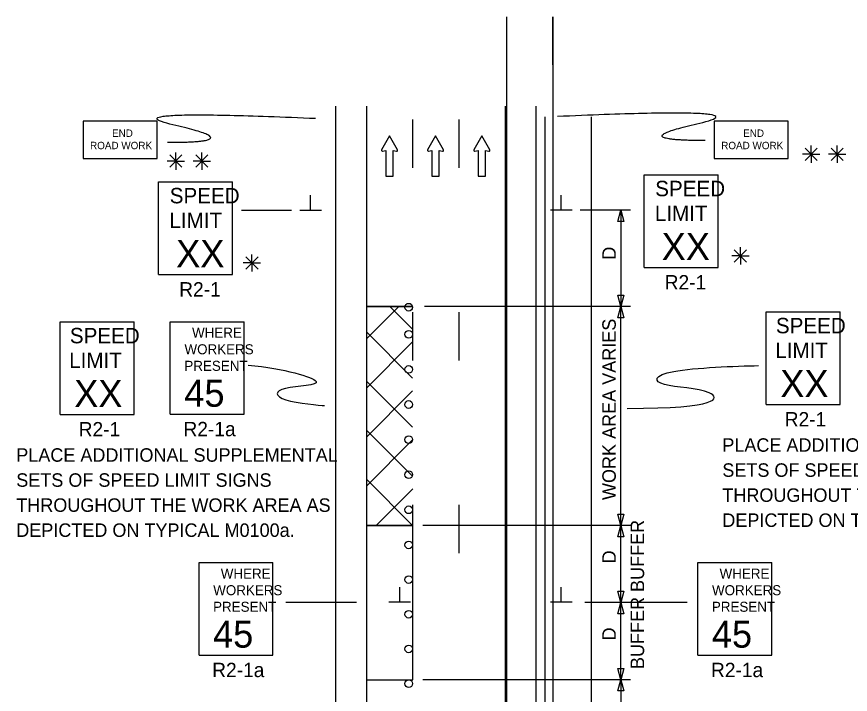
# Model space of a CAD drawing. Extents: x 16590 to 19504, y 5703 to 6974.
# Drawn here: x 16726.2 to 17159.2, y 6622.4 to 6974.1 of the extents above; entities that cross this region are included whole.
import ezdxf

# ---------------------------------------------------------------- set-up
doc = ezdxf.new("R2010")
doc.units = 0
for name, color, linetype in [('ALI_LEGAL_EX', 7, 'Continuous'), ('MT_SCRATCH_LEVEL_E', 7, 'Continuous'), ('PAVT_EDGE_EX', 7, 'Continuous'), ('TRAFFIC_SIGNS_PR', 7, 'Continuous'), ('TYPICAL_TEXT_DIMEN_PR', 7, 'Continuous')]:
    doc.layers.add(name, color=color, linetype=linetype)

msp = doc.modelspace()

# ---------------------------------------------------------------- linework, layer by layer
at = {"layer": 'ALI_LEGAL_EX'}
for p, q in [((16980.68, 6974.12), (16980.68, 6155.98)), ((17004.68, 6974.12), (17004.68, 6155.98)), ((17000.61, 6922.21), (17000.61, 6058.3)), ((17024.61, 6922.21), (17024.61, 6058.3))]:
    msp.add_line(p, q, dxfattribs=at)
for points in [[(17004.68, 6949.12), (17004.68, 6974.12)], [(16931.89, 6920.69), (16931.89, 6895.69)], [(16955.89, 6920.69), (16955.89, 6895.69)], [(16931.89, 6820.69), (16931.89, 6795.69)], [(16955.89, 6820.69), (16955.89, 6795.69)], [(16931.89, 6720.69), (16931.89, 6695.69)], [(16955.89, 6720.69), (16955.89, 6695.69)]]:
    msp.add_lwpolyline(points, dxfattribs=at)
at = {"layer": 'MT_SCRATCH_LEVEL_E'}
for p, q in [((16919.89, 6912.2), (16915.78, 6904.96)), ((16924.03, 6904.96), (16919.89, 6912.2)), ((16943.79, 6912.2), (16939.68, 6904.96)), ((16947.94, 6904.96), (16943.79, 6912.2)), ((16967.84, 6912.2), (16963.73, 6904.96)), ((16971.99, 6904.96), (16967.84, 6912.2)), ((16916.26, 6904.28), (16918.04, 6904.59)), ((16918.04, 6904.59), (16918.04, 6891.34)), ((16921.78, 6891.34), (16921.78, 6904.59)), ((16921.78, 6904.59), (16923.56, 6904.28)), ((16940.16, 6904.28), (16941.94, 6904.59)), ((16941.94, 6904.59), (16941.94, 6891.34)), ((16945.68, 6891.34), (16945.68, 6904.59)), ((16945.68, 6904.59), (16947.46, 6904.28)), ((16964.22, 6904.28), (16965.99, 6904.59)), ((16965.99, 6904.59), (16965.99, 6891.34)), ((16969.73, 6891.34), (16969.73, 6904.59)), ((16969.73, 6904.59), (16971.51, 6904.28)), ((16918.04, 6891.34), (16921.78, 6891.34)), ((16941.94, 6891.34), (16945.68, 6891.34)), ((16965.99, 6891.34), (16969.73, 6891.34))]:
    msp.add_line(p, q, dxfattribs=at)
for centre, start, end in [((16916.18, 6904.74), 150.4248, 279.9638), ((16923.62, 6904.74), 260.0362, 29.7731), ((16940.09, 6904.74), 150.4248, 279.9638), ((16947.53, 6904.74), 260.0362, 29.7731), ((16964.14, 6904.74), 150.4248, 279.9638), ((16971.58, 6904.74), 260.0362, 29.7731)]:
    msp.add_arc(centre, 0.463, start, end, dxfattribs=at)
at = {"layer": 'PAVT_EDGE_EX'}
for p, q in [((16891.89, 6927.73), (16891.89, 6507.47)), ((16907.89, 6927.73), (16907.89, 6507.47)), ((16979.89, 6927.73), (16979.89, 6507.47)), ((16995.89, 6927.73), (16995.89, 6507.47)), ((16907.89, 6823.76), (16931.89, 6823.76)), ((16907.89, 6806.86), (16924.79, 6823.76)), ((16931.98, 6823.76), (16907.98, 6823.76)), ((16931.89, 6811.94), (16920.07, 6823.76)), ((16931.89, 6786.49), (16907.89, 6810.49)), ((16907.89, 6781.4), (16931.89, 6805.4)), ((16931.89, 6761.03), (16907.89, 6785.03)), ((16907.89, 6755.95), (16931.89, 6779.95)), ((16931.89, 6735.58), (16907.89, 6759.58)), ((16907.89, 6730.49), (16931.89, 6754.49)), ((16931.89, 6710.12), (16907.89, 6734.12)), ((16912.88, 6710.03), (16931.98, 6729.12)), ((16931.89, 6710.03), (16907.89, 6710.03)), ((16931.98, 6710.03), (16907.98, 6710.03)), ((16907.98, 6710.03), (16931.98, 6710.03))]:
    msp.add_line(p, q, dxfattribs=at)
msp.add_lwpolyline([(16931.94, 6710.13), (16907.89, 6710.13), (16907.89, 6630.03), (16931.94, 6630.03)], close=True, dxfattribs=at)
at = {"layer": 'TRAFFIC_SIGNS_PR'}
for p, q in [((17052.11, 6892.08), (17090.56, 6892.08)), ((17052.11, 6844.02), (17052.11, 6892.08)), ((17090.56, 6844.02), (17090.56, 6892.08)), ((16799.93, 6888.4), (16838.38, 6888.4)), ((16799.93, 6840.34), (16799.93, 6888.4)), ((16838.38, 6840.34), (16838.38, 6888.4)), ((17052.11, 6844.02), (17090.56, 6844.02)), ((16799.93, 6840.34), (16838.38, 6840.34)), ((17115.56, 6820.92), (17153.96, 6820.92)), ((17115.56, 6772.92), (17115.56, 6820.92)), ((17153.96, 6772.92), (17153.96, 6820.92)), ((16748.8, 6815.74), (16787.2, 6815.74)), ((16748.8, 6767.74), (16748.8, 6815.74)), ((16787.2, 6767.74), (16787.2, 6815.74)), ((16806, 6815.83), (16844.4, 6815.83)), ((16806, 6767.83), (16806, 6815.83)), ((16844.4, 6767.83), (16844.4, 6815.83)), ((17115.56, 6772.92), (17153.96, 6772.92)), ((16748.8, 6767.74), (16787.2, 6767.74)), ((16806, 6767.83), (16844.4, 6767.83)), ((16820.92, 6690.79), (16859.32, 6690.79)), ((16820.92, 6642.79), (16820.92, 6690.79)), ((16859.32, 6642.79), (16859.32, 6690.79)), ((17080.02, 6690.79), (17118.42, 6690.79)), ((17080.02, 6642.79), (17080.02, 6690.79)), ((17118.42, 6642.79), (17118.42, 6690.79)), ((16820.92, 6642.79), (16859.32, 6642.79)), ((17080.02, 6642.79), (17118.42, 6642.79))]:
    msp.add_line(p, q, dxfattribs=at)
for points in [[(16760.72, 6900.6), (16799.17, 6900.6), (16799.17, 6919.82), (16760.72, 6919.82)], [(17088.57, 6900.6), (17127.02, 6900.6), (17127.02, 6919.82), (17088.57, 6919.82)]]:
    msp.add_lwpolyline(points, close=True, dxfattribs=at)
for centre in [(16929.88, 6823.35), (16929.88, 6809.27), (16929.88, 6791.05), (16929.88, 6772.84), (16929.88, 6754.62), (16929.88, 6736.41), (16929.88, 6718.19), (16929.88, 6699.98), (16929.88, 6681.98), (16929.88, 6663.98), (16929.88, 6645.98), (16929.88, 6627.98)]:
    msp.add_circle(centre, 2, dxfattribs=at)
for points in [[(16804.64, 6908.91), (16847.16, 6908.91), (16770.64, 6926.32), (16881.42, 6921.38)], [(17083.85, 6909.83), (17041.34, 6909.83), (17117.86, 6927.24), (17007.07, 6922.3)]]:
    msp.add_open_spline(points, degree=2, dxfattribs=at)
at = {"layer": 'TYPICAL_TEXT_DIMEN_PR'}
for p, q in [((17138.9, 6902.72), (17138.9, 6907.18)), ((17152.41, 6902.72), (17152.41, 6907.18)), ((16808.9, 6899.17), (16808.9, 6903.63)), ((16822.4, 6899.17), (16822.4, 6903.63)), ((17138.9, 6902.72), (17134.37, 6902.72)), ((17135.72, 6905.91), (17142.09, 6899.53)), ((17142.09, 6905.91), (17135.72, 6899.53)), ((17138.9, 6902.72), (17142.09, 6902.72)), ((17138.9, 6902.72), (17143.38, 6902.72)), ((17138.9, 6902.72), (17138.9, 6898.22)), ((17152.41, 6902.72), (17147.88, 6902.72)), ((17149.22, 6905.91), (17155.6, 6899.53)), ((17155.6, 6905.91), (17149.22, 6899.53)), ((17152.41, 6902.72), (17155.6, 6902.72)), ((17152.41, 6902.72), (17156.89, 6902.72)), ((17152.41, 6902.72), (17152.41, 6898.22)), ((16808.9, 6899.17), (16804.36, 6899.17)), ((16805.71, 6902.36), (16812.08, 6895.99)), ((16812.08, 6902.36), (16805.71, 6895.99)), ((16808.9, 6899.17), (16812.08, 6899.17)), ((16808.9, 6899.17), (16813.37, 6899.17)), ((16808.9, 6899.17), (16808.9, 6894.67)), ((16822.4, 6899.17), (16817.87, 6899.17)), ((16825.59, 6902.36), (16819.21, 6895.99)), ((16819.22, 6902.36), (16825.59, 6895.99)), ((16822.4, 6899.17), (16825.59, 6899.17)), ((16822.4, 6899.17), (16826.88, 6899.17)), ((16822.4, 6899.17), (16822.4, 6894.67)), ((16878.85, 6873.76), (16878.85, 6881.54)), ((17009.1, 6873.76), (17009.1, 6881.54)), ((16842.98, 6873.76), (16868.98, 6873.76)), ((16873.23, 6873.76), (16884.48, 6873.76)), ((17014.73, 6873.76), (17003.48, 6873.76)), ((17044.98, 6873.76), (17018.98, 6873.76)), ((17038.41, 6867.9), (17039.98, 6873.76)), ((17039.98, 6873.76), (17039.98, 6823.76)), ((17039.98, 6873.76), (17041.55, 6867.9)), ((17039.98, 6867.9), (17038.41, 6867.9)), ((17041.55, 6867.9), (17039.98, 6867.9)), ((16848.44, 6846.29), (16848.44, 6850.74)), ((17098.97, 6853.15), (17105.34, 6846.78)), ((17105.34, 6853.15), (17098.97, 6846.78)), ((17102.16, 6849.97), (17102.16, 6854.42)), ((16848.44, 6846.29), (16843.91, 6846.29)), ((16851.63, 6849.47), (16845.25, 6843.1)), ((16845.26, 6849.47), (16851.63, 6843.1)), ((16848.44, 6846.29), (16851.63, 6846.29)), ((16848.44, 6846.29), (16852.92, 6846.29)), ((16848.44, 6846.29), (16848.44, 6841.79)), ((17102.16, 6849.97), (17097.62, 6849.97)), ((17102.16, 6849.97), (17105.34, 6849.97)), ((17102.16, 6849.97), (17106.63, 6849.97)), ((17102.16, 6849.97), (17102.16, 6845.47)), ((17039.98, 6823.76), (17038.41, 6829.62)), ((17038.41, 6829.62), (17039.98, 6829.62)), ((17039.98, 6829.62), (17041.55, 6829.62)), ((17041.55, 6829.62), (17039.98, 6823.76)), ((17044.98, 6823.76), (16937.97, 6823.76)), ((17038.41, 6817.9), (17039.98, 6823.76)), ((17039.98, 6710.03), (17039.98, 6823.76)), ((17039.98, 6823.76), (17041.55, 6817.9)), ((17039.98, 6817.9), (17038.41, 6817.9)), ((17041.55, 6817.9), (17039.98, 6817.9)), ((17039.98, 6710.03), (17038.41, 6715.9)), ((17038.41, 6715.9), (17039.98, 6715.9)), ((17039.98, 6715.9), (17041.55, 6715.9)), ((17041.55, 6715.9), (17039.98, 6710.03)), ((17044.98, 6710.03), (16937.27, 6710.03)), ((17038.41, 6704.17), (17039.98, 6710.03)), ((17039.98, 6670.03), (17039.98, 6710.03)), ((17039.98, 6710.03), (17041.55, 6704.17)), ((17039.98, 6704.17), (17038.41, 6704.17)), ((17041.55, 6704.17), (17039.98, 6704.17)), ((16925.18, 6670.25), (16925.18, 6678.04)), ((17009.1, 6670.25), (17009.1, 6678.04)), ((17039.98, 6670.03), (17038.41, 6675.9)), ((17038.41, 6675.9), (17039.98, 6675.9)), ((17039.98, 6675.9), (17041.55, 6675.9)), ((17041.55, 6675.9), (17039.98, 6670.03)), ((16902.74, 6670.03), (16866.02, 6670.03)), ((16930.81, 6670.25), (16919.56, 6670.25)), ((17014.73, 6670.25), (17003.48, 6670.25)), ((17074.57, 6670.03), (17021.28, 6670.03)), ((17038.41, 6664.17), (17039.98, 6670.03)), ((17039.98, 6630.03), (17039.98, 6670.03)), ((17039.98, 6670.03), (17041.55, 6664.17)), ((17039.98, 6664.17), (17038.41, 6664.17)), ((17041.55, 6664.17), (17039.98, 6664.17)), ((17039.98, 6630.03), (17038.41, 6635.9)), ((17038.41, 6635.9), (17039.98, 6635.9)), ((17039.98, 6635.9), (17041.55, 6635.9)), ((17041.55, 6635.9), (17039.98, 6630.03)), ((17044.98, 6630.03), (16937.27, 6630.03)), ((17038.41, 6624.17), (17039.98, 6630.03)), ((17039.98, 6630.03), (17039.89, 6537.98)), ((17039.98, 6630.03), (17041.55, 6624.17)), ((17039.98, 6624.17), (17038.41, 6624.17)), ((17041.55, 6624.17), (17039.98, 6624.17))]:
    msp.add_line(p, q, dxfattribs=at)
for points in [[(16846.51, 6793.34), (16865.38, 6791.56), (16894.98, 6782.59), (16860.06, 6782.59), (16860.06, 6774.39), (16883.91, 6772.45), (16886.16, 6772.3)], [(17043.29, 6770.83), (17091.75, 6770.83), (17091.75, 6781.59), (17056.84, 6781.59), (17056.84, 6791.25), (17099.7, 6792.77), (17111.61, 6793.03)]]:
    msp.add_open_spline(points, degree=3, dxfattribs=at)

# ---------------------------------------------------------------- texts
at = {"layer": 'TRAFFIC_SIGNS_PR'}
for s, height, p in [('END', 3.836, (16775.74, 6911.74)), ('END', 3.836, (17103.59, 6911.74)), ('ROAD WORK', 3.836, (16764.33, 6905.35)), ('ROAD WORK', 3.836, (17092.18, 6905.35)), ('SPEED', 8.01, (16805.71, 6877.25)), ('SPEED', 8.01, (17057.89, 6880.93)), ('LIMIT', 8.01, (16805.55, 6864.43)), ('LIMIT', 8.01, (17057.72, 6868.11)), ('XX', 14.048, (17061.24, 6847.78)), ('XX', 14.048, (16809.06, 6844.1)), ('R2-1', 7.449, (17062.8, 6832.56)), ('R2-1', 7.449, (16810.62, 6828.89)), ('SPEED', 8, (17120.59, 6809.79)), ('SPEED', 8, (16753.84, 6804.6)), ('WHERE', 5.2, (16817.31, 6807.51)), ('WORKERS', 5.2, (16813.38, 6798.91)), ('LIMIT', 8, (17120.26, 6796.99)), ('LIMIT', 8, (16753.5, 6791.8)), ('PRESENT', 5.2, (16813.31, 6790.31)), ('XX', 14.031, (17122.87, 6776.68)), ('45', 14.031, (16813.3, 6771.68)), ('XX', 14.031, (16756.11, 6771.5)), ('R2-1', 7.44, (17125.17, 6761.48)), ('R2-1', 7.44, (16758.41, 6756.3)), ('R2-1a', 7.44, (16812.85, 6756.39)), ('PLACE ADDITIONAL SUPPLEMENTAL', 7, (17092.76, 6748.31)), ('PLACE ADDITIONAL SUPPLEMENTAL', 7, (16726, 6743.13)), ('SETS OF SPEED LIMIT SIGNS', 7, (17092.76, 6735.31)), ('SETS OF SPEED LIMIT SIGNS', 7, (16726, 6730.13)), ('THROUGHOUT THE WORK AREA AS', 7, (17092.76, 6722.31)), ('THROUGHOUT THE WORK AREA AS', 7, (16726, 6717.13)), ('DEPICTED ON TYPICAL M0100a.', 7, (17092.76, 6709.31)), ('DEPICTED ON TYPICAL M0100a.', 7, (16726, 6704.13)), ('WHERE', 5.2, (16832.23, 6682.47)), ('WHERE', 5.2, (17091.33, 6682.47)), ('WORKERS', 5.2, (16828.3, 6673.87)), ('WORKERS', 5.2, (17087.4, 6673.87)), ('PRESENT', 5.2, (16828.23, 6665.27)), ('PRESENT', 5.2, (17087.33, 6665.27)), ('45', 14.031, (16828.22, 6646.64)), ('45', 14.031, (17087.33, 6646.64)), ('R2-1a', 7.44, (16827.77, 6631.35)), ('R2-1a', 7.44, (17086.87, 6631.35))]:
    msp.add_text(s, height=height, dxfattribs=at).set_placement(p)
at = {"layer": 'TYPICAL_TEXT_DIMEN_PR'}
for s, p in [('D', (17037.42, 6847.98)), ('WORK AREA VARIES', (17037.42, 6723.25)), ('BUFFER', (17052.14, 6675.54)), ('D', (17037.42, 6690.37)), ('BUFFER', (17052.14, 6635.54)), ('D', (17037.42, 6650.37))]:
    msp.add_text(s, height=7, rotation=90, dxfattribs=at).set_placement(p)

doc.saveas('drawing.dxf')
